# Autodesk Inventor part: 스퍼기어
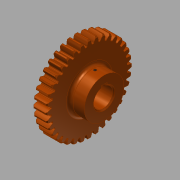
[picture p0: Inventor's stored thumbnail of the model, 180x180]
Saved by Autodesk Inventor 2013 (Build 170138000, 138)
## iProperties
Created: 2019-01
Part Number: 스퍼기어
Material: 알루미늄 6061
Document SubType Name: Modeling
Designer: mduedu
Density: 1 g/cm^3
Author: mduedu
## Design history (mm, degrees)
sketch "스케치1"
  geometry: C1 r 33.5 at (0, 0); 1 further point
  constraints: 1 centre point, 1 coincident
  dimensions: "d0" = 67 diameter of C1
extrude "돌출1" new body sketch "스케치1" stored distance "d2" = 12; taper "d3" = 0 deg
sketch "스케치2" dims "d4" = 72
  geometry: L1 (0, 0)-(-38, 0); L2 (0, 0)-(0, 38); L3 (-0.57, 0)-(-0.57, 37.996); L4 (-1.57, 0)-(-1.57, 37.968); L5 (-2.07, 0)-(-2.07, 37.944); C1 r 33.5 at (0, 0); A1 r 38 centre (0, 0) between (-38, 0) and (0, 38); A2 r 9.246 centre (7.162, 32.926) between (-0.57, 37.996) and (-2.07, 33.436); A3 r 9.246 centre (-7.162, 32.926) between (2.07, 33.436) and (0.57, 37.996); A4 r 33.5 centre (0, 0) between (2.07, 33.436) and (-2.07, 33.436); A5 r 38 centre (0, 0) between (0.57, 37.996) and (-0.57, 37.996); 3 further points
  constraints: 14 point on circle, 10 end point, 6 centre point, 5 coincident, 5 point on line, 3 symmetric about line, 2 parallel, 2 perpendicular, 1 horizontal, 7 other
  dimensions: "d6" = 76 diameter of A1; "d7" = 0.5 distance between parallel lines of L4 L5; "d8" = 1 distance between parallel lines of L3 L4; "d9" = 1.57 distance between parallel lines of L2 L4
extrude "돌출2" join sketch "스케치2" stored distance "d10" = 0; taper "d11" = 0 deg
chamfer "모따기1" distance "d12" = 1; stored, may be unused: second distance "d13" = 2, angle "d14" = 45 deg
fillet "모깎기1" dims "d15" = 0.5
sketch "스케치3"
  geometry: C1 r 17.5 at (0, 0); 1 further point
  constraints: 1 centre point, 1 coincident
  dimensions: "d19" = 35 diameter of C1
extrude "돌출3" join sketch "스케치3" distance "d20" = 13; taper "d21" = 0 deg
sketch "스케치4"
  geometry: L1 (-2.5, 8.124)-(2.5, 8.124); L2 (2.5, 8.124)-(2.5, 10.8); L3 (2.5, 10.8)-(-2.5, 10.8); L4 (-2.5, 10.8)-(-2.5, 8.124); A1 r 8.5 centre (0, 0) between (-2.5, 8.124) and (2.5, 8.124); 1 further point
  constraints: 8 end point, 2 parallel, 2 point on circle, 1 centre point, 1 coincident, 1 horizontal, 1 perpendicular
  dimensions: "d22" = 17 diameter of A1; "d23" = 5 distance of L2.end L3.end; "d24" = 19.3 dimension on A1 L3
extrude "돌출4" cut sketch "스케치4" stored distance "d25" = 13; taper "d26" = 0 deg
sketch "스케치5"
  geometry: C1 r 15 at (0, 0); C2 r 27.5 at (0, 0); 1 further point
  constraints: 2 centre point, 2 coincident
  dimensions: "d33" = 30 diameter of C1; "d34" = 55 diameter of C2
extrude "돌출5" cut sketch "스케치5" distance "d30" = 6; taper "d31" = 0 deg
fillet "모깎기2" dims "d32" = 3
node "작업 평면1"
sketch "스케치6"
  geometry: L1 (17.5, 13)-(-17.5, 13) reference; 2 further points
  constraints: 1 vertical alignment
  dimensions: "d35" = 8 distance from line of point (0, 5) L1
hole "구멍1" sketch "스케치6" at (0, 5) diameter "d36" = 2.459; stored, may be unused: countersink angle "d40" = 90 deg, drill point angle "d42" = 118 deg; dims "d37" = 6, "d38" = 4, "d39" = 2, "d41" = 8
fillet "모깎기3" dims "d43" = 3
chamfer "모따기2" distance "d44" = 1; stored, may be unused: second distance "d45" = 2, angle "d46" = 45 deg
node "솔리드1"
pattern_circular "원형 패턴1" dims "d17" = 360 deg
